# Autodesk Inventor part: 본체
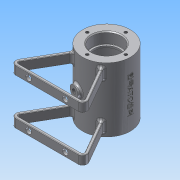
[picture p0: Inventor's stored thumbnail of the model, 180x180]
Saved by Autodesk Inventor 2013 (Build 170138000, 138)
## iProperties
Created: 2016-03
Part Number: 본체
Material: 알루미늄 6061
Document SubType Name: Modeling
Designer: Administrator
Density: 2.71 g/cm^3
Mass: 213.146 g
Surface Area: 333.934 cm^2
Volume: 78.6515 cm^3
Author: Administrator
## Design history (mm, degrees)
sketch "스케치1"
  geometry: C1 r 26 at (0, 0); 1 further point
  constraints: 1 centre point, 1 coincident
  dimensions: "d0" = 52 diameter of C1
extrude "돌출1" new body sketch "스케치1" stored distance "d1" = 70; taper "d2" = 0 deg
node "작업 평면1"
sketch "스케치3"
  geometry: L1 (0, -65)-(33.934, -65); L2 (0, -65)-(-33.934, -65); L3 (-16.613, -20)-(-38.264, -57.5); L4 (16.613, -20)-(38.264, -57.5); L5 (35.666, -59)-(15.685, -24.392); L6 (-15.685, -24.392)-(-35.666, -59); L7 (-33.934, -62)-(0, -62); L8 (0, -62)-(33.934, -62); L9 (15.685, -24.392)-(14.183, -21.791); L10 (-15.685, -24.392)-(-14.183, -21.791); A1 r 26 centre (0, 0) between (16.613, -20) and (-16.613, -20) reference; A2 r 5 centre (-33.934, -60) between (-38.264, -57.5) and (-33.934, -65); A3 r 5 centre (33.934, -60) between (33.934, -65) and (38.264, -57.5); A4 r 2 centre (-33.934, -60) between (-35.666, -59) and (-33.934, -62); A5 r 2 centre (33.934, -60) between (33.934, -62) and (35.666, -59); A6 r 26 centre (0, 0) between (-16.613, -20) and (-14.183, -21.791); A7 r 26 centre (0, 0) between (14.183, -21.791) and (16.613, -20); 3 further points
  constraints: 20 end point, 14 point on circle, 6 centre point, 4 collinear, 4 point on line, 4 tangent, 1 coincident, 1 equal radius, 4 other
  dimensions: "d33" = 45 vertical distance of point (42.594, -65) L4.start; "d34" = 45 vertical distance of point (-42.594, -65) L3.start; "d37" = 5 radius of A2; "d38" = 3 distance between parallel lines of L4 L5
extrude "돌출2" join sketch "스케치3" distance "d39" = 10; taper "d40" = 0 deg
sketch "스케치4"
  geometry: C1 r 26 at (0, 0) reference; C2 r 16 at (0, 0)
  constraints: 1 centre point, 1 coincident
  dimensions: "d41" = 32 diameter of C2
extrude "돌출3" cut sketch "스케치4" distance "d42" = 12; taper "d43" = 0 deg
sketch "스케치5"
  geometry: C1 r 16 at (0, 0) reference; C2 r 14 at (0, 0)
  constraints: 1 centre point, 1 coincident
  dimensions: "d44" = 28 diameter of C2
extrude "돌출4" cut sketch "스케치5" distance "d45" = 2; taper "d46" = 0 deg
sketch "스케치6"
  geometry: L1 (0, 0)-(0, 21); C1 r 26 at (0, 0) reference
  constraints: 2 end point, 1 coincident, 1 vertical alignment, 2 other
hole "구멍1" sketch "스케치6" at (0, 21) diameter "d48" = 3.242; stored, may be unused: countersink angle "d52" = 90 deg, drill point angle "d54" = 118 deg; dims "d49" = 8, "d50" = 4, "d51" = 2, "d53" = 10
node "작업 평면2"
sketch "스케치7"
  geometry: C1 r 21 at (0, 0); 1 further point
  constraints: 1 centre point, 1 coincident
  dimensions: "d58" = 42 diameter of C1
extrude "돌출5" cut sketch "스케치7" stored distance "d59" = 42; taper "d60" = 0 deg
sketch "스케치8"
  geometry: L1 (0, 0)-(67.868, 0) reference; L2 (67.868, -10)-(0, -10) reference; L3 (33.934, -10)-(33.934, -5); C1 r 3 at (53.934, -5); C2 r 3 at (13.934, -5); 1 further point
  constraints: 2 centre point, 2 end point, 1 midpoint, 1 perpendicular
  dimensions: "d63" = 6 diameter of C1; "d65" = 6 diameter of C2
extrude "돌출6" cut sketch "스케치8" distance "d66" = 20; taper "d67" = 0 deg
node "작업 평면3"
sketch "스케치9"
  geometry: L1 (26, 35)-(-26, 35) reference; L2 (0, 35)-(0, 0); C1 r 5 at (0, 0)
  constraints: 2 end point, 1 centre point, 1 coincident, 1 midpoint, 1 perpendicular
  dimensions: "d69" = 35 distance of L2.start L2.end (derived); "d70" = 10 diameter of C1
extrude "돌출7" join sketch "스케치9" stored distance "d71" = 20; taper "d72" = 0 deg
sketch "스케치10"
  geometry: C1 r 5 at (0, 0) reference
hole "구멍2" sketch "스케치10" at (0, 0) diameter "d73" = 5.188; stored, may be unused: countersink angle "d77" = 90 deg, drill point angle "d79" = 118 deg; dims "d74" = 8, "d75" = 4, "d76" = 2, "d78" = 10
sketch "스케치11"
  geometry: L1 (0, 0)-(0, -44.243); L2 (0, 0)-(-7.506, -28.012)
  constraints: 4 end point, 1 vertical
  dimensions: "d80" = 29 distance of L1.start L2.end; "d81" = 15 deg angle of L1 L2
node "작업 평면4"
sketch "스케치12"
  geometry: C1 r 6 at (0, 0); 1 further point
  constraints: 1 centre point, 1 coincident
  dimensions: "d82" = 12 diameter of C1
extrude "돌출8" join sketch "스케치12" stored distance "d83" = 20; taper "d84" = 0 deg
sketch "스케치13"
  geometry: C1 r 6 at (0, 0) reference
hole "구멍3" sketch "스케치13" at (0, 0) diameter "d85" = 5.188; stored, may be unused: countersink angle "d89" = 90 deg, drill point angle "d91" = 118 deg; dims "d86" = 8, "d87" = 4, "d88" = 2, "d90" = 10
node "작업 평면5"
sketch "스케치14"
  geometry: L1 (26, 35)-(-26, 35) reference; 2 further points
  constraints: 1 other
feature "엠보싱1" sketch "스케치14" dims "d33" = 45, "d34" = 45, "d37" = 5, "d38" = 3, "d95" = 0.5, "d96" = 0
chamfer "모따기1" distance "d97" = 1; stored, may be unused: second distance "d98" = 2, angle "d99" = 45 deg
fillet "모깎기2" dims "d102" = 0.5, "d103" = 0.3, "d104" = 3, "d105" = 2
node "솔리드1"
pattern_circular "원형 패턴1" dims angle "d56" = 360 deg
mirror "대칭1"
mirror "대칭2"
other parameters: "d68" = 29, "d92" = 45.25
